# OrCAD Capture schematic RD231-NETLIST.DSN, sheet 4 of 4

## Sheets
4 1: size A3
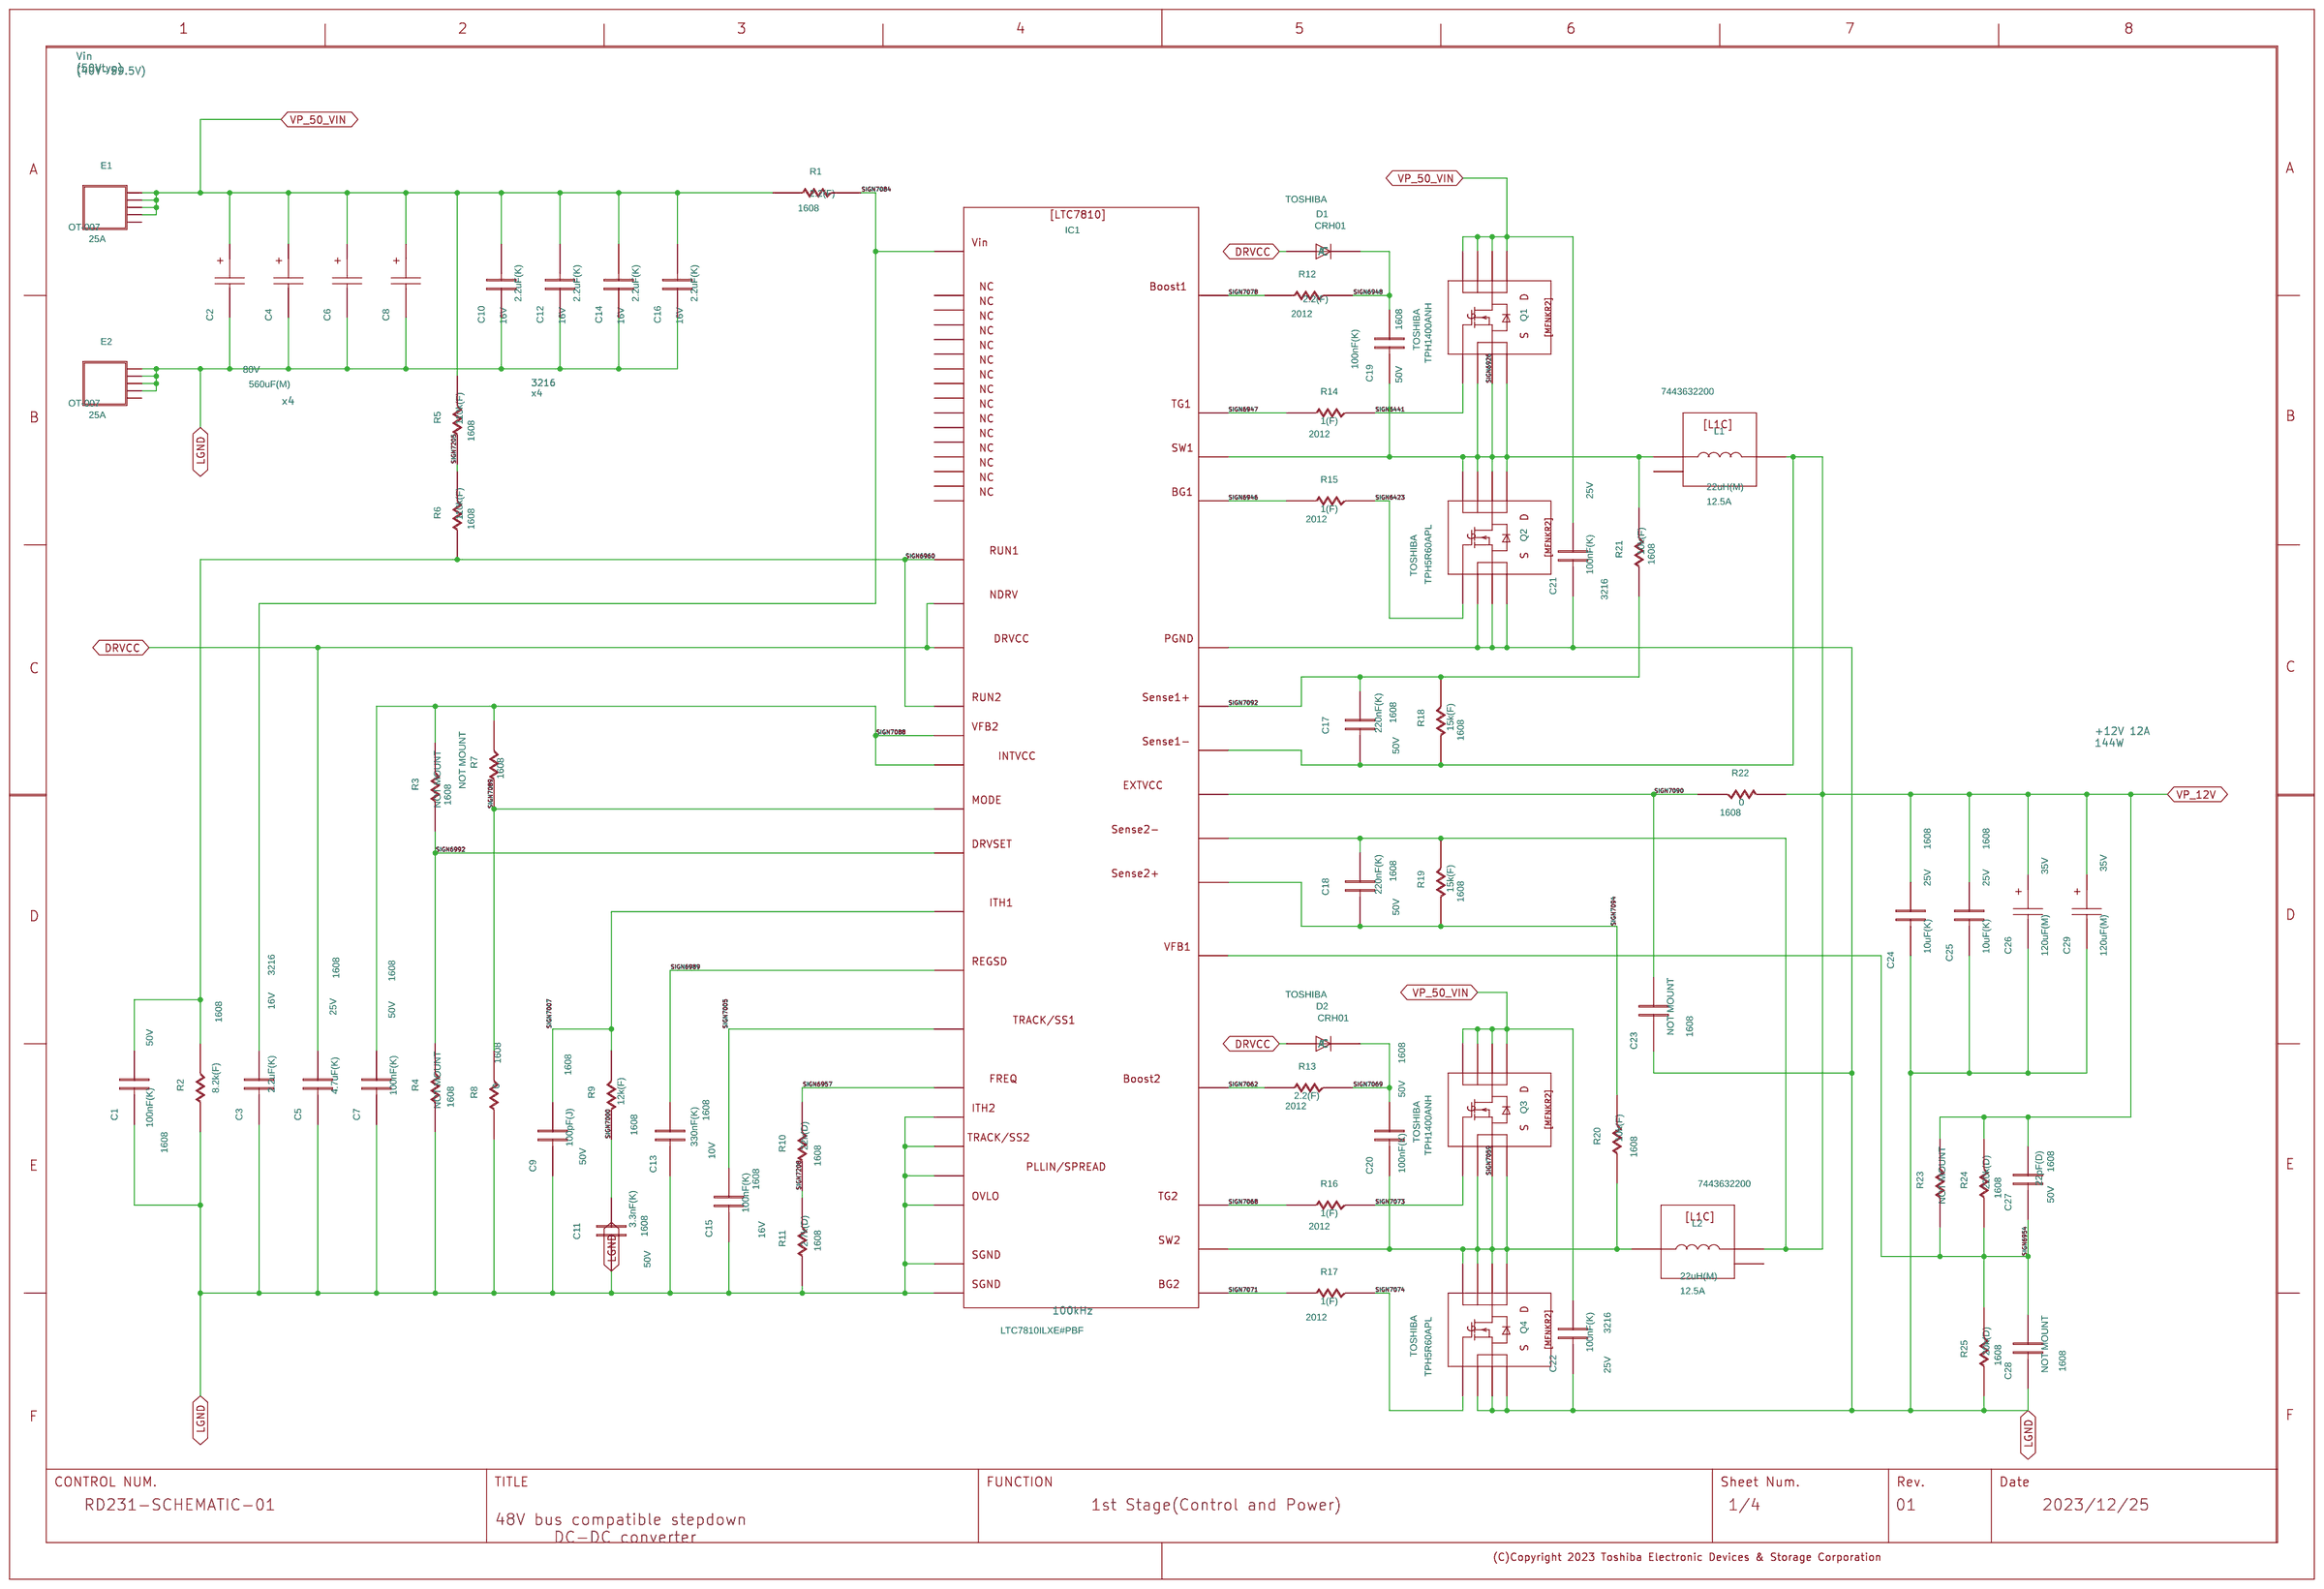
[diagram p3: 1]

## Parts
C1  C
C2  CP
C3  C
C4  CP
C5  C
C6  CP
C7  C
C8  CP
C9  C
C10  C
C11  C
C12  C
C13  C
C14  C
C15  C
C16  C
C17  C
C18  C
C19  C
C20  C
C21  C
C22  C
C23  C
C24  C
C25  C
C26  CP
C27  C
C28  C
C29  CP
D1  D
D2  D
E1  EB
E2  EB
IC1  LTC7810_1
L1  L1C
L2  L1C
Q1  MFNKR2
Q2  MFNKR2
Q3  MFNKR2
Q4  MFNKR2
R1  R
R2  R
R3  R
R4  R
R5  R
R6  R
R7  R
R8  R
R9  R
R10  R
R11  R
R12  R
R13  R
R14  R
R15  R
R16  R
R17  R
R18  R
R19  R
R20  R
R21  R
R22  R
R23  R
R24  R
R25  R
U?#3  WAKU_DEF100

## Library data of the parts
C1 C7 C19 C20 = C: COMP: GDM030001005; COMPONENTNAME: GDM030001005_package; COMPONENTTYPE: 4; FNCLASSCODEG: P03-03; FNPARTSNAMEG: CHIP CERAMIC CAPACITOR (1608); FUNCN: GDM030001005; GCOUNT: 1; MAXGCOUNT: 1; MFFORMINGDIVP: KC; MFMOUNTSYMBOLP: 80; MFPACKAGEMETHOP: S; MFSOLDERINGPROP: .; PARTCOMMENT: ã\Z<KC0008> ªtbgvgÉo^³êÄ¢Ü¹ñB; PCODE: P03B000001KW; SIZECODESMD: 1608; USEINPARTSLIST: YES; USEWITHLAYOUT: YES; USEWITHSCHEMA: YES; VAL1: 100nF(K); VAL2: 50V
C2 C4 C6 C8 = CP: COMP: G36030155199; COMPONENTNAME: G36030155199_package; COMPONENTTYPE: 4; FNCLASSCODEG: P03-01; FNPARTSCODEG: C; FNPARTSNAMEG: CHIP ALUMINUM ELECTROLYTIC CAPACITOR; FUNCN: G36030155199; GCOUNT: 1; MAXGCOUNT: 1; MFFORMINGDIVP: KD; MFMOUNTSYMBOLP: 80; MFPACKAGEMETHOP: S; MFSOLDERINGPROP: F; OUMEPARTTYPE: C; PCODE: P03090017118; USEINPARTSLIST: YES; USEWITHLAYOUT: YES; USEWITHSCHEMA: YES; VAL1: 560uF(M); VAL2: 80V
C3 C10 C12 C14 C16 = C: COMP: G36030110013; COMPONENTNAME: G36030110013_package; COMPONENTTYPE: 4; FNCLASSCODEG: P03-03; FNPARTSNAMEG: CHIP CERAMIC CAPACITOR (3216); FUNCN: G36030110013; GCOUNT: 1; MAXGCOUNT: 1; MFFORMINGDIVP: KC; MFMOUNTSYMBOLP: 90; MFPACKAGEMETHOP: S; MFSOLDERINGPROP: .; PCODE: P03042997321; SIZECODESMD: 3216; TOLERANCE: K; USEINPARTSLIST: YES; USEWITHLAYOUT: YES; USEWITHSCHEMA: YES; VAL1: 2.2uF(K); VAL2: 16V
C5 = C: COMP: GDM030001182; COMPONENTNAME: GDM030001182_package; COMPONENTTYPE: 4; FNCLASSCODEG: P03-03; FNPARTSNAMEG: CHIP CERAMIC CAPACITOR (1608); FUNCN: GDM030001182; GCOUNT: 1; MAXGCOUNT: 1; MFFORMINGDIVP: KC; MFMOUNTSYMBOLP: 80; MFPACKAGEMETHOP: S; MFSOLDERINGPROP: .; PARTCOMMENT: ã\Z<KC0008> ªtbgvgÉo^³êÄ¢Ü¹ñB; PCODE: P03B000001NY; SIZECODESMD: 1608; USEINPARTSLIST: YES; USEWITHLAYOUT: YES; USEWITHSCHEMA: YES; VAL1: 4.7uF(K); VAL2: 25V
C9 = C: COMP: G36030011181; COMPONENTNAME: G36030011181_package; COMPONENTTYPE: 4; FNCLASSCODEG: P03-03; FNPARTSNAMEG: CHIP CERAMIC CAPACITOR (1608); FUNCN: G36030011181; GCOUNT: 1; MAXGCOUNT: 1; MFFORMINGDIVP: KC; MFMOUNTSYMBOLP: 80; MFPACKAGEMETHOP: S; MFSOLDERINGPROP: .; PCODE: P03039307126; SIZECODESMD: 1608; TOLERANCE: J; USEINPARTSLIST: YES; USEWITHLAYOUT: YES; USEWITHSCHEMA: YES; VAL1: 100pF(J); VAL2: 50V
C11 = C: COMP: G36030011075; COMPONENTNAME: G36030011075_package; COMPONENTTYPE: 4; FNCLASSCODEG: P03-03; FNPARTSNAMEG: CHIP CERAMIC CAPACITOR (1608); FUNCN: G36030011075; GCOUNT: 1; MAXGCOUNT: 1; MFFORMINGDIVP: KC; MFMOUNTSYMBOLP: 80; MFPACKAGEMETHOP: S; MFSOLDERINGPROP: .; PCODE: P03039A11122; SIZECODESMD: 1608; TOLERANCE: K; USEINPARTSLIST: YES; USEWITHLAYOUT: YES; USEWITHSCHEMA: YES; VAL1: 3.3nF(K); VAL2: 50V
C13 = C: COMP: G36030104111; COMPONENTNAME: G36030104111_package; COMPONENTTYPE: 4; FNCLASSCODEG: P03-03; FNPARTSNAMEG: CHIP CERAMIC CAPACITOR (1608); FUNCN: G36030104111; GCOUNT: 1; MAXGCOUNT: 1; MFFORMINGDIVP: KC; MFMOUNTSYMBOLP: 80; MFPACKAGEMETHOP: S; MFSOLDERINGPROP: .; PCODE: P03039ABF120; SIZECODESMD: 1608; USEINPARTSLIST: YES; USEWITHLAYOUT: YES; USEWITHSCHEMA: YES; VAL1: 330nF(K); VAL2: 10V
C15 = C: COMP: G36030011419; COMPONENTNAME: G36030011419_package; COMPONENTTYPE: 4; FNCLASSCODEG: P03-03; FNPARTSNAMEG: CHIP CERAMIC CAPACITOR (1608); FUNCN: G36030011419; GCOUNT: 1; MAXGCOUNT: 1; MFFORMINGDIVP: KC; MFMOUNTSYMBOLP: 80; MFPACKAGEMETHOP: S; MFSOLDERINGPROP: .; PCODE: P03039996139; SIZECODESMD: 1608; USEINPARTSLIST: YES; USEWITHLAYOUT: YES; USEWITHSCHEMA: YES; VAL1: 100nF(K); VAL2: 16V
C17 C18 = C: COMP: G36030104128; COMPONENTNAME: G36030104128_package; COMPONENTTYPE: 4; FNCLASSCODEG: P03-03; FNPARTSNAMEG: CHIP CERAMIC CAPACITOR (1608); FUNCN: G36030104128; GCOUNT: 1; MAXGCOUNT: 1; MFFORMINGDIVP: KC; MFMOUNTSYMBOLP: 80; MFPACKAGEMETHOP: S; MFSOLDERINGPROP: .; PCODE: P03039ABG127; SIZECODESMD: 1608; USEINPARTSLIST: YES; USEWITHLAYOUT: YES; USEWITHSCHEMA: YES; VAL1: 220nF(K); VAL2: 50V
C21 C22 = C: COMP: G36030031080; COMPONENTNAME: G36030031080_package; COMPONENTTYPE: 4; FNCLASSCODEG: P03-03; FNPARTSNAMEG: CHIP CERAMIC CAPACITOR (3216); FUNCN: G36030031080; GCOUNT: 1; MAXGCOUNT: 1; MFFORMINGDIVP: KC; MFMOUNTSYMBOLP: 90; MFPACKAGEMETHOP: S; MFSOLDERINGPROP: .; PCODE: P03042006320; SIZECODESMD: 3216; TOLERANCE: K; USEINPARTSLIST: YES; USEWITHLAYOUT: YES; USEWITHSCHEMA: YES; VAL1: 100nF(K); VAL2: 25V
C23 = C: COMP: GDM030001005; COMPONENTNAME: GDM030001005_package; COMPONENTTYPE: 4; FNCLASSCODEG: P03-03; FNPARTSNAMEG: CHIP CERAMIC CAPACITOR (1608); FUNCN: GDM030001005; GCOUNT: 1; MAXGCOUNT: 1; MFFORMINGDIVP: KC; MFMOUNTSYMBOLP: 80; MFPACKAGEMETHOP: S; MFSOLDERINGPROP: .; NOTMOUNT: NOT MOUNT; PARTCOMMENT: ã\Z<KC0008> ªtbgvgÉo^³êÄ¢Ü¹ñB; PCODE: P03B000001KW; SIZECODESMD: 1608; USEINPARTSLIST: YES; USEWITHLAYOUT: YES; USEWITHSCHEMA: YES
C24 C25 = C: COMP: GDM030000053; COMPONENTNAME: GDM030000053_package; COMPONENTTYPE: 4; FNCLASSCODEG: P03-03; FNPARTSNAMEG: CHIP CERAMIC CAPACITOR (1608); FUNCN: GDM030000053; GCOUNT: 1; MAXGCOUNT: 1; MFFORMINGDIVP: KC; MFMOUNTSYMBOLP: 80; MFPACKAGEMETHOP: S; MFSOLDERINGPROP: .; PCODE: P03B000000MS; SIZECODESMD: 1608; USEINPARTSLIST: YES; USEWITHLAYOUT: YES; USEWITHSCHEMA: YES; VAL1: 10uF(K); VAL2: 25V
C26 C29 = CP: COMP: G36030155199; COMPONENTNAME: G36030155199_package; COMPONENTTYPE: 4; FNCLASSCODEG: P03-01; FNPARTSCODEG: C; FNPARTSNAMEG: CHIP ALUMINUM ELECTROLYTIC CAPACITOR; FUNCN: G36030155199; GCOUNT: 1; MAXGCOUNT: 1; MFFORMINGDIVP: KD; MFMOUNTSYMBOLP: 80; MFPACKAGEMETHOP: S; MFSOLDERINGPROP: F; OUMEPARTTYPE: C; PCODE: P03090017118; USEINPARTSLIST: YES; USEWITHLAYOUT: YES; USEWITHSCHEMA: YES; VAL1: 120uF(M); VAL2: 35V
C27 = C: COMP: G36030011013; COMPONENTNAME: G36030011013_package; COMPONENTTYPE: 4; FNCLASSCODEG: P03-03; FNPARTSNAMEG: CHIP CERAMIC CAPACITOR (1608); FUNCN: G36030011013; GCOUNT: 1; MAXGCOUNT: 1; MFFORMINGDIVP: KC; MFMOUNTSYMBOLP: 80; MFPACKAGEMETHOP: S; MFSOLDERINGPROP: .; PCODE: P03039185229; SIZECODESMD: 1608; TOLERANCE: D; USEINPARTSLIST: YES; USEWITHLAYOUT: YES; USEWITHSCHEMA: YES; VAL1: 22pF(D); VAL2: 50V
C28 = C: COMP: G36030011013; COMPONENTNAME: G36030011013_package; COMPONENTTYPE: 4; FNCLASSCODEG: P03-03; FNPARTSNAMEG: CHIP CERAMIC CAPACITOR (1608); FUNCN: G36030011013; GCOUNT: 1; MAXGCOUNT: 1; MFFORMINGDIVP: KC; MFMOUNTSYMBOLP: 80; MFPACKAGEMETHOP: S; MFSOLDERINGPROP: .; NOTMOUNT: NOT MOUNT; PCODE: P03039185229; SIZECODESMD: 1608; TOLERANCE: D; USEINPARTSLIST: YES; USEWITHLAYOUT: YES; USEWITHSCHEMA: YES
D1 D2 = D: COMP: 5P9L1110P002; COMPONENTTYPE: 4; OUMEMAKER: “ŒŽÅ; OUMEMAKERKATAMEI: CMF02(TE12R,Q); SAVEAREA0: -565,-171,12979,8058; USEINPARTSLIST: YES; USERCOMPTEXT3: TOSHIBA; USEWITHLAYOUT: YES; USEWITHSCHEMA: YES; VAL1: 1A; VAL2: 200V; VAL3: CRH01
E1 E2 = EB: COMP: 5P9L1232P001; COMPONENTTYPE: 4; VAL1: 25A; VAL3: OT-007
IC1 = LTC7810_1: COMP: LTC7810ILXE#PBF; COMPONENTNAME: LTC7810_1.LTC7810_1; COMPONENTTYPE: 4; GCOUNT: 1; MAXGCOUNT: 1; OUMEMAKERKATAMEI: LTC7810ILXE#PBF; USEINPARTSLIST: YES; USEWITHLAYOUT: YES; USEWITHSCHEMA: YES; VAL1: LTC7810ILXE#PBF; VAL3: LTC7810ILXE#PBF
L1 L2 = L1C: COMP: 7443630140; COMPONENTNAME: L1C_L1C; COMPONENTTYPE: 8; GCOUNT: 1; MAXGCOUNT: 1; OUMEMAKER: WURTH; OUMEMAKERKATAMEI: 7443630140; USEINPARTSLIST: YES; USEWITHLAYOUT: YES; USEWITHSCHEMA: YES; VAL1: 22uH(M); VAL2: 12.5A; VAL3: 7443632200
Q1 Q3 = MFNKR2: COMP: TPH6R003NL; COMPONENTNAME: MFNKR2_MFNKR2; COMPONENTTYPE: 4; GCOUNT: 1; MAXGCOUNT: 1; OUMEMAKER: TOSHIBA; OUMEMAKERKATAMEI: TPH6R003NL; USEINPARTSLIST: YES; USERCOMPTEXT3: TOSHIBA; USEWITHLAYOUT: YES; USEWITHSCHEMA: YES; VAL1: TPH1400ANH; VAL3: TPH1400ANH
Q2 Q4 = MFNKR2: COMP: TPH6R003NL; COMPONENTNAME: MFNKR2_MFNKR2; COMPONENTTYPE: 4; GCOUNT: 1; MAXGCOUNT: 1; OUMEMAKER: TOSHIBA; OUMEMAKERKATAMEI: TPH6R003NL; USEINPARTSLIST: YES; USERCOMPTEXT3: TOSHIBA; USEWITHLAYOUT: YES; USEWITHSCHEMA: YES; VAL1: TPH5R60APL; VAL3: TPH5R60APL
R1 = R: COMP: G36010141013; COMPONENTNAME: G36010141013_package; COMPONENTTYPE: 4; FNCLASSCODEG: P01-08; FNPARTSNAMEG: CHIP RESISTOR (1608); FUNCN: G36010141013; MFFORMINGDIVP: KC; MFMOUNTSYMBOLP: 80; MFPACKAGEMETHOP: S; MFSOLDERINGPROP: .; NUMBEROFELEMENT: 0; PCODE: P01183001112; SIZECODESMD: 1608; USEINPARTSLIST: YES; USEWITHLAYOUT: YES; USEWITHSCHEMA: YES; VAL1: 2.2(F); VAL2: 100mW
R2 = R: COMP: G36010027188; COMPONENTNAME: G36010027188_package; COMPONENTTYPE: 4; FNCLASSCODEG: P01-08; FNPARTSNAMEG: CHIP RESISTOR (1608); FUNCN: G36010027188; GCOUNT: 1; MAXGCOUNT: 1; MFFORMINGDIVP: KC; MFMOUNTSYMBOLP: 80; MFPACKAGEMETHOP: S; MFSOLDERINGPROP: .; NUMBEROFELEMENT: 0; PCODE: P01042507328; SIZECODESMD: 1608; TOLERANCE: F; USEINPARTSLIST: YES; USEWITHLAYOUT: YES; USEWITHSCHEMA: YES; VAL1: 8.2k(F); VAL2: 100mW
R3 R4 = R: COMP: G36010027034; COMPONENTNAME: G36010027034_package; COMPONENTTYPE: 4; FNCLASSCODEG: P01-08; FNPARTSNAMEG: CHIP RESISTOR (1608); FUNCN: G36010027034; GCOUNT: 1; MAXGCOUNT: 1; MFFORMINGDIVP: KC; MFMOUNTSYMBOLP: 80; MFPACKAGEMETHOP: S; MFSOLDERINGPROP: .; NOTMOUNT: NOT MOUNT; NUMBEROFELEMENT: 0; PCODE: P01042049A26; SIZECODESMD: 1608; TOLERANCE: F; USEINPARTSLIST: YES; USEWITHLAYOUT: YES; USEWITHSCHEMA: YES
R5 R6 = R: COMP: G36010027300; COMPONENTNAME: G36010027300_package; COMPONENTTYPE: 4; FNCLASSCODEG: P01-08; FNPARTSNAMEG: CHIP RESISTOR (1608); FUNCN: G36010027300; GCOUNT: 1; MAXGCOUNT: 1; MFFORMINGDIVP: KC; MFMOUNTSYMBOLP: 80; MFPACKAGEMETHOP: S; MFSOLDERINGPROP: .; NUMBEROFELEMENT: 0; PCODE: P01042519628; SIZECODESMD: 1608; TOLERANCE: F; USEINPARTSLIST: YES; USEWITHLAYOUT: YES; USEWITHSCHEMA: YES; VAL1: 110k(F); VAL2: 100mW
R7 = R: COMP: G36010027133; COMPONENTNAME: G36010027133_package; COMPONENTTYPE: 4; FNCLASSCODEG: P01-08; FNPARTSNAMEG: CHIP RESISTOR (1608); FUNCN: G36010027133; GCOUNT: 1; MAXGCOUNT: 1; MFFORMINGDIVP: KC; MFMOUNTSYMBOLP: 80; MFPACKAGEMETHOP: S; MFSOLDERINGPROP: .; NOTMOUNT: NOT MOUNT; NUMBEROFELEMENT: 0; PCODE: P01042045226; SIZECODESMD: 1608; TOLERANCE: F; USEINPARTSLIST: YES; USEWITHLAYOUT: YES; USEWITHSCHEMA: YES
R8 = R: COMP: G36010027089; COMPONENTNAME: G36010027089_package; COMPONENTTYPE: 4; FNCLASSCODEG: P01-08; FNPARTSNAMEG: CHIP RESISTOR (1608); FUNCN: G36010027089; GCOUNT: 1; MAXGCOUNT: 1; MFFORMINGDIVP: KC; MFMOUNTSYMBOLP: 80; MFPACKAGEMETHOP: S; MFSOLDERINGPROP: .; NUMBEROFELEMENT: 0; PCODE: P01042207426; SIZECODESMD: 1608; TOLERANCE: F; USEINPARTSLIST: YES; USEWITHLAYOUT: YES; USEWITHSCHEMA: YES; VAL1: 0
R9 = R: COMP: G36010027041; COMPONENTNAME: G36010027041_package; COMPONENTTYPE: 4; FNCLASSCODEG: P01-08; FNPARTSNAMEG: CHIP RESISTOR (1608); FUNCN: G36010027041; GCOUNT: 1; MAXGCOUNT: 1; MFFORMINGDIVP: KC; MFMOUNTSYMBOLP: 80; MFPACKAGEMETHOP: S; MFSOLDERINGPROP: .; NUMBEROFELEMENT: 0; PCODE: P01042097423; SIZECODESMD: 1608; TOLERANCE: F; USEINPARTSLIST: YES; USEWITHLAYOUT: YES; USEWITHSCHEMA: YES; VAL1: 12k(F); VAL2: 100mW
R10 = R: COMP: G36010129578; COMPONENTNAME: G36010129578_package; COMPONENTTYPE: 4; FNCLASSCODEG: P01-08; FNPARTSNAMEG: CHIP RESISTOR (1608); FUNCN: G36010129578; GCOUNT: 1; MAXGCOUNT: 1; MFFORMINGDIVP: KC; MFMOUNTSYMBOLP: 80; MFPACKAGEMETHOP: S; MFSOLDERINGPROP: .; NUMBEROFELEMENT: 0; PCODE: P01119059118; SIZECODESMD: 1608; USEINPARTSLIST: YES; USEWITHLAYOUT: YES; USEWITHSCHEMA: YES; VAL1: 22k(D); VAL2: 62.5mW
R11 = R: COMP: G36010129356; COMPONENTNAME: G36010129356_package; COMPONENTTYPE: 4; FNCLASSCODEG: P01-08; FNPARTSNAMEG: CHIP RESISTOR (1608); FUNCN: G36010129356; GCOUNT: 1; MAXGCOUNT: 1; MFFORMINGDIVP: KC; MFMOUNTSYMBOLP: 80; MFPACKAGEMETHOP: S; MFSOLDERINGPROP: .; NUMBEROFELEMENT: 0; PCODE: P01117039112; SIZECODESMD: 1608; USEINPARTSLIST: YES; USEWITHLAYOUT: YES; USEWITHSCHEMA: YES; VAL1: 2.7k(D); VAL2: 62.5mW
R12 R13 = R: COMP: G36010106012; COMPONENTNAME: G36010106012_package; COMPONENTTYPE: 4; FNCLASSCODEG: P01-08; FNPARTSNAMEG: CHIP RESISTOR (2012); FUNCN: G36010106012; GCOUNT: 1; MAXGCOUNT: 1; MFFORMINGDIVP: KC; MFMOUNTSYMBOLP: 90; MFPACKAGEMETHOP: S; MFSOLDERINGPROP: .; NUMBEROFELEMENT: 0; PCODE: P01048019214; SIZECODESMD: 2012; USEINPARTSLIST: YES; USEWITHLAYOUT: YES; USEWITHSCHEMA: YES; VAL1: 2.2(F); VAL2: 125mW
R14-R17 = R: COMP: G36010106081; COMPONENTNAME: G36010106081_package; COMPONENTTYPE: 4; FNCLASSCODEG: P01-08; FNPARTSNAMEG: CHIP RESISTOR (2012); FUNCN: G36010106081; GCOUNT: 1; MAXGCOUNT: 1; MFFORMINGDIVP: KC; MFMOUNTSYMBOLP: 90; MFPACKAGEMETHOP: S; MFSOLDERINGPROP: .; NUMBEROFELEMENT: 0; PCODE: P01048017210; SIZECODESMD: 2012; USEINPARTSLIST: YES; USEWITHLAYOUT: YES; USEWITHSCHEMA: YES; VAL1: 1(F); VAL2: 125mW
R18 R19 = R: COMP: G36010027058; COMPONENTNAME: G36010027058_package; COMPONENTTYPE: 4; FNCLASSCODEG: P01-08; FNPARTSNAMEG: CHIP RESISTOR (1608); FUNCN: G36010027058; GCOUNT: 1; MAXGCOUNT: 1; MFFORMINGDIVP: KC; MFMOUNTSYMBOLP: 80; MFPACKAGEMETHOP: S; MFSOLDERINGPROP: .; NUMBEROFELEMENT: 0; PCODE: P01042113727; SIZECODESMD: 1608; TOLERANCE: F; USEINPARTSLIST: YES; USEWITHLAYOUT: YES; USEWITHSCHEMA: YES; VAL1: 15k(F); VAL2: 100mW
R20 R21 = R: COMP: G5101105R107; COMPONENTNAME: G5101105R107_package; COMPONENTTYPE: 4; FNCLASSCODEG: P01-08; FNPARTSNAMEG: CHIP RESISTOR (1608); FUNCN: G5101105R107; GCOUNT: 1; MAXGCOUNT: 1; MFFORMINGDIVP: KC; MFMOUNTSYMBOLP: 80; MFPACKAGEMETHOP: S; MFSOLDERINGPROP: .; NUMBEROFELEMENT: 0; PCODE: P01042424625; SIZECODESMD: 1608; USEINPARTSLIST: YES; USEWITHLAYOUT: YES; USEWITHSCHEMA: YES; VAL1: 10k(F); VAL2: 100mW
R22 = R: COMP: K0100346; COMPONENTNAME: K0100346_package; COMPONENTTYPE: 4; FNCLASSCODEG: P01-08; FNPARTSNAMEG: CHIP JUMPER 1608TYPE; FUNCN: K0100346; GCOUNT: 1; MAXGCOUNT: 1; PARTCOMMENT: ã\Z<KC0008> ªtbgvgÉo^³êÄ¢Ü¹ñB; SIZECODESMD: 1608; USEINPARTSLIST: YES; USEWITHLAYOUT: YES; USEWITHSCHEMA: YES; VAL1: 0
R23 = R: COMP: G5101106F106; COMPONENTNAME: G5101106F106_package; COMPONENTTYPE: 4; FNCLASSCODEG: P01-08; FNPARTSNAMEG: CHIP RESISTOR (1608); FUNCN: G5101106F106; GCOUNT: 1; MAXGCOUNT: 1; MFFORMINGDIVP: KC; MFMOUNTSYMBOLP: 80; MFPACKAGEMETHOP: S; MFSOLDERINGPROP: .; NOTMOUNT: NOT MOUNT; NUMBEROFELEMENT: 0; PCODE: P01042680229; SIZECODESMD: 1608; USEINPARTSLIST: YES; USEWITHLAYOUT: YES; USEWITHSCHEMA: YES
R24 = R: COMP: G5101109J104; COMPONENTNAME: G5101109J104_package; COMPONENTTYPE: 4; FNCLASSCODEG: P01-08; FNPARTSNAMEG: CHIP RESISTOR (1608); FUNCN: G5101109J104; GCOUNT: 1; MAXGCOUNT: 1; MFFORMINGDIVP: KC; MFMOUNTSYMBOLP: 80; MFPACKAGEMETHOP: S; MFSOLDERINGPROP: .; NUMBEROFELEMENT: 0; PCODE: P01042669620; SIZECODESMD: 1608; USEINPARTSLIST: YES; USEWITHLAYOUT: YES; USEWITHSCHEMA: YES; VAL1: 220k(D); VAL2: 62.5mW
R25 = R: COMP: G36010129493; COMPONENTNAME: G36010129493_package; COMPONENTTYPE: 4; FNCLASSCODEG: P01-08; FNPARTSNAMEG: CHIP RESISTOR (1608); FUNCN: G36010129493; GCOUNT: 1; MAXGCOUNT: 1; MFFORMINGDIVP: KC; MFMOUNTSYMBOLP: 80; MFPACKAGEMETHOP: S; MFSOLDERINGPROP: .; NUMBEROFELEMENT: 0; PCODE: P01117053118; SIZECODESMD: 1608; USEINPARTSLIST: YES; USEWITHLAYOUT: YES; USEWITHSCHEMA: YES; VAL1: 20k(D); VAL2: 62.5mW
U?#3 = WAKU_DEF100: AUTHOR: d9000436; COMPONENTTYPE: 2; DATE: 2023/12/25; DRAWINGNUMBER: RD231-SCHEMATIC-01; FUNCTION: 1st Stage(Control and Power); REVISION: 01; SAVEAREA0: -56280,0,471144,298016; SHEETNUMBER: 1/4; TIME: 20:22:11; TITLE: 48V bus compatible stepdown / DC-DC converter; UPDATEDATE: 2024/01/12; UPDATETIME: 11:34:32; UPDATEUSER: sptcae13

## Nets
DRVCC: C5.1 D1.1(A) D2.1(A) IC1.10 IC1.26
LGND: C1.2 C2.1 C3.2 C4.1 C5.2 C6.1 C7.2 C8.1 C9.2 C10.1 C11.2 C12.1 C13.2 C14.1 C15.2 C16.1 C21.2 C22.2 C23.2 C24.2 C25.2 C26.1 C28.2 C29.1 E2.1 E2.2 E2.3 E2.4 IC1.4 IC1.5 IC1.9 IC1.15 IC1.16 IC1.25 IC1.49 Q2.1 Q2.2 Q2.3 Q4.1 Q4.2 Q4.3 R2.1 R4.1 R8.1 R11.1 R25.1 ; also on sheet 1 2 3
SIGN6423: Q2.4 R15.2
SIGN6441: Q1.4 R14.2
SIGN6926: C19.2 IC1.41 L1.1 Q1.1 Q1.2 Q1.3 Q2.5 Q2.6 Q2.7 Q2.8 R21.2
SIGN6946: IC1.37 R15.1
SIGN6947: IC1.42 R14.1
SIGN6948: C19.1 D1.2(C) R12.2
SIGN6954: C27.2 C28.1 IC1.47 R23.1 R24.1 R25.2
SIGN6957: IC1.6 R10.2
SIGN6960: C1.1 IC1.29 IC1.32 R2.2 R6.1
SIGN6989: C13.1 IC1.7
SIGN6992: IC1.2 R3.1 R4.2
SIGN7000: C11.1 R9.1
SIGN7005: C15.1 IC1.45
SIGN7007: C9.1 IC1.46 R9.2
SIGN7059: C20.2 IC1.20 L2.2 Q3.1 Q3.2 Q3.3 Q4.5 Q4.6 Q4.7 Q4.8 R20.1
SIGN7062: IC1.21 R13.1
SIGN7068: IC1.19 R16.1
SIGN7069: C20.1 D2.2(C) R13.2
SIGN7071: IC1.24 R17.1
SIGN7073: Q3.4 R16.2
SIGN7074: Q4.4 R17.2
SIGN7078: IC1.40 R12.1
SIGN7084: C3.1 IC1.35 R1.2
SIGN7088: C7.1 IC1.3 IC1.14 R3.2 R7.2
SIGN7089: IC1.8 R7.1 R8.2
SIGN7090: C23.1 IC1.11 R22.2
SIGN7092: C17.1 IC1.48 R18.2 R21.1
SIGN7094: C18.2 IC1.13 R19.1 R20.2
SIGN7205: R5.1 R6.2
SIGN7208: R10.1 R11.2
VP_12V: C17.2 C18.1 C24.1 C25.1 C26.2 C27.1 C29.2 IC1.1 IC1.12 L1.2 L2.1 R18.1 R19.2 R22.1 R23.2 R24.2 ; also on sheet 1 2
VP_50_VIN: C2.2 C4.2 C6.2 C8.2 C10.2 C12.2 C14.2 C16.2 C21.1 C22.1 E1.1 E1.2 E1.3 E1.4 Q1.5 Q1.6 Q1.7 Q1.8 Q3.5 Q3.6 Q3.7 Q3.8 R1.1 R5.2

Not connected (* = marked no-connect by the designer): E1 5; E2 5; IC1 17 18 22 23 27 28 30 31 33 34 36 38 39 43 44; L1 3; L2 3

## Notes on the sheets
sheet 4
- Vin
  (50Vtyp)
- (40V-59.5V)
- 3216
  x4
- x4
- +12V 12A
  144W
- 100kHz
